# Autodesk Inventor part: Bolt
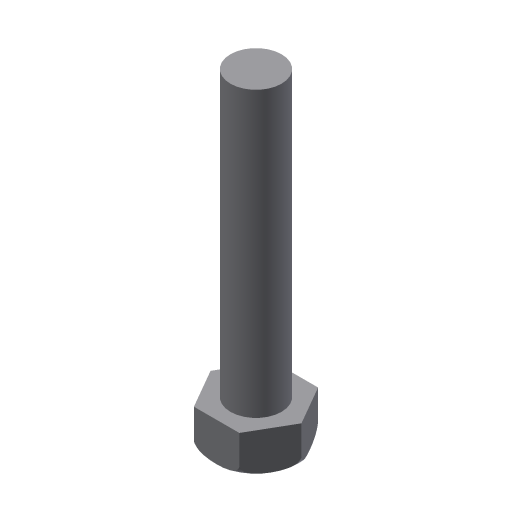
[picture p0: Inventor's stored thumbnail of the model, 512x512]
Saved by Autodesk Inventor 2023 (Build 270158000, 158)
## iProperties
Created: 2002-02
Part Number: Bolt
Document SubType Name: Modeling
Designer: ***
Density: 1 g/cm^3
Material: Generic
Appearance: Default
Control State: 0
Master: False
Checked Out: False
Shininess: 77.0
Length Units: 11269
Angle Units: 11279
Time Units: 11290
Mass Units: 11283
Length Display Precision: 3
Angle Display Precision: 2
Density: 0.0
Volumn: 0.0
Area: 0.0
PropertySet Name: Model Information
Author: ***
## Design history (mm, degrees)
sketch "Sketch1"
  geometry: C1 r 4 at (0, 0)
  constraints: 1 centre point
  dimensions: "d0" = 8 diameter of C1
extrude "Extrusion1" new body sketch "Sketch1" stored distance "d1" = 3.5; taper "d2" = 0 deg
fillet "Fillet1" dims "d3" = 1
sketch "Sketch2"
  geometry: L1 (4, 0)-(2, -3.464); L2 (2, -3.464)-(-2, -3.464); L3 (-2, -3.464)-(-4, 0); L4 (-4, 0)-(-2, 3.464); L5 (-2, 3.464)-(2, 3.464); L6 (2, 3.464)-(4, 0); 2 further points
  constraints: 12 end point, 1 coincident, 11 other
extrude "Extrusion2" sketch "Sketch2" extent not by distance; stored distance "d4" = 3.5; taper "d5" = 0 deg
sketch "Sketch3"
  geometry: C1 r 2.25 at (0, 0)
  constraints: 1 centre point
  dimensions: "d6" = 4.5 diameter of C1
extrude "Extrusion3" join sketch "Sketch3" distance "d7" = 25; taper "d8" = 0 deg
body "Solid1"
